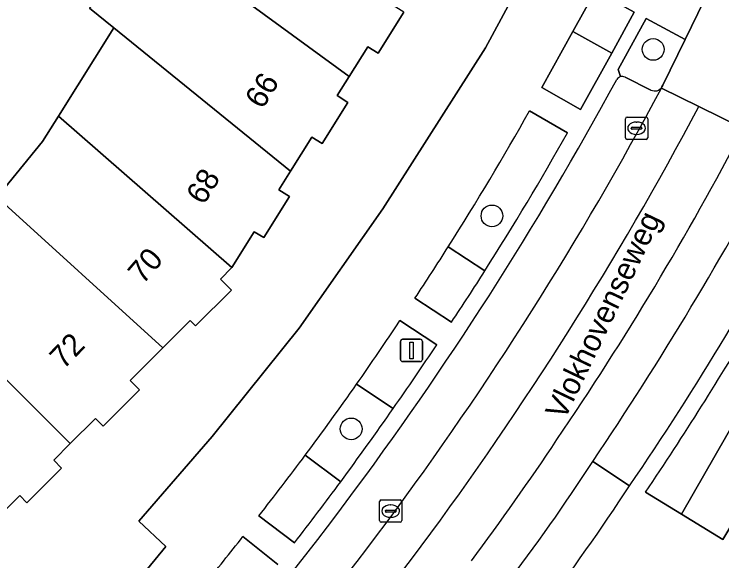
# Model space of a CAD drawing. Extents: x 161354 to 162026, y 386504 to 387460.
# Drawn here: x 161596.6 to 161628.46, y 386881.71 to 386906.3 of the extents above; entities that cross this region are included whole.
import ezdxf

# ---------------------------------------------------------------- set-up
doc = ezdxf.new("R2010")
doc.units = 0
for name, color, linetype in [('IMGEO_Boom', 7, 'Continuous'), ('IMGEO_Erf', 7, 'Continuous'), ('IMGEO_Groenvoorziening', 7, 'Continuous'), ('IMGEO_Kolk', 7, 'Continuous'), ('IMGEO_Lichtmast', 7, 'Continuous'), ('IMGEO_Openbare_ruimte_label', 7, 'Continuous'), ('IMGEO_Pand', 7, 'Continuous'), ('IMGEO_Pand_nummerreeks', 7, 'Continuous'), ('IMGEO_Parkeervlak_open', 7, 'Continuous'), ('IMGEO_Rijbaan_lokaal_gesloten', 7, 'Continuous'), ('IMGEO_Rijbaan_lokaal_open', 7, 'Continuous'), ('IMGEO_Voetpad_open', 7, 'Continuous')]:
    doc.layers.add(name, color=color, linetype=linetype)

msp = doc.modelspace()

# ---------------------------------------------------------------- linework, layer by layer
at = {"layer": 'IMGEO_Boom'}
for centre in [(161625.366, 386904.718), (161618.11, 386897.228), (161611.772, 386887.643)]:
    msp.add_circle(centre, 0.489, dxfattribs=at)
at = {"layer": 'IMGEO_Erf'}
for points in [[(161601.088, 386879.5), (161603.425, 386882.36), (161602.205, 386883.499), (161605.511, 386887.3), (161609.426, 386892.17), (161613.199, 386897.541), (161617.812, 386904.79), (161621.155, 386910.96), (161615.666, 386914.035), (161613.626, 386916.073), (161610.545, 386917.769), (161608.974, 386918.547), (161607.34, 386919.182), (161605.655, 386919.668), (161604.896, 386919.835), (161603.346, 386920.042), (161602.754, 386919.169), (161601.089, 386916.715), (161599.424, 386914.261), (161597.317, 386915.691), (161595.992, 386913.34), (161598.099, 386911.91), (161596.434, 386909.456)], [(161614.148, 386906.394), (161612.989, 386904.544), (161612.517, 386904.84), (161611.674, 386903.494), (161611.14, 386902.642), (161611.628, 386902.336), (161610.467, 386900.482), (161610.001, 386900.774), (161609.038, 386899.236), (161608.514, 386898.399), (161608.991, 386898.1), (161607.832, 386896.25), (161607.409, 386896.515), (161606.397, 386894.899), (161605.885, 386894.387), (161606.378, 386893.893), (161604.76, 386892.278), (161604.522, 386892.517), (161603.288, 386891.286), (161601.818, 386889.818), (161602.236, 386889.399), (161600.605, 386887.771), (161600.261, 386888.116), (161599.124, 386886.982), (161598.38, 386886.239), (161598.735, 386885.884), (161597.172, 386884.323), (161596.848, 386884.648), (161595.588, 386883.391)], [(161595.815, 386898.067), (161597.876, 386900.568), (161598.596, 386901.718), (161601.082, 386905.687), (161599.987, 386906.575)]]:
    msp.add_lwpolyline(points, dxfattribs=at)
at = {"layer": 'IMGEO_Groenvoorziening'}
for points in [[(161624.515, 386906.389), (161622.768, 386907.364), (161621.746, 386905.523), (161623.499, 386904.549)], [(161621.746, 386905.523), (161620.349, 386903.005), (161622.102, 386902.02), (161623.499, 386904.549)], [(161633.249, 386890.619), (161631.253, 386891.827), (161626.635, 386883.81), (161628.505, 386882.663)]]:
    msp.add_lwpolyline(points, close=True, dxfattribs=at)
for points in [[(161626.801, 386905.161), (161625.051, 386906.108), (161623.791, 386903.815), (161623.901, 386903.492)], [(161625.763, 386903.031), (161625.799, 386903.114), (161626.801, 386905.161)], [(161624.099, 386903.472), (161625.268, 386902.889)], [(161621.512, 386900.967), (161619.798, 386901.947)], [(161616.143, 386895.841), (161617.793, 386894.758)], [(161617.793, 386894.758), (161616.143, 386895.841)], [(161614.64, 386893.523), (161616.289, 386892.447)], [(161615.622, 386891.432), (161613.966, 386892.515)], [(161625.025, 386884.797), (161626.635, 386883.81), (161631.253, 386891.827)], [(161613.664, 386888.559), (161612.012, 386889.653)], [(161612.012, 386889.653), (161613.664, 386888.559)], [(161609.701, 386886.457), (161611.3, 386885.271)], [(161611.3, 386885.271), (161609.701, 386886.457)], [(161607.615, 386883.731), (161609.221, 386882.526)], [(161608.476, 386881.546), (161606.897, 386882.798)]]:
    msp.add_lwpolyline(points, dxfattribs=at)
for centre, radius, start, end in [((161623.973, 386903.219), 0.282, 63.602, 104.8622), ((161625.44, 386903.222), 0.375, 242.5924, 329.4206), ((161500.36, 386969.295), 137.118, 327.60864, 330.5826), ((161504.13, 386967.057), 134.708, 327.54032, 330.61906), ((161497.522, 386971.109), 140.486, 326.47711, 327.60384), ((161502.238, 386968.316), 136.981, 326.36724, 327.52057), ((161498.371, 386969.338), 138.795, 324.96181, 326.39241), ((161490.613, 386975.069), 161.913, 326.11426, 329.38467), ((161486.034, 386977.645), 155.646, 325.08494, 326.36482), ((161497.604, 386969.947), 139.772, 323.32124, 324.93803), ((161488.847, 386975.806), 152.287, 323.52286, 325.04652), ((161491.692, 386974.599), 147.293, 321.90829, 323.24356), ((161490.956, 386974.257), 149.67, 322.20143, 323.51966), ((161486.485, 386977.923), 153.453, 320.64443, 321.69126)]:
    msp.add_arc(centre, radius, start, end, dxfattribs=at)
at = {"layer": 'IMGEO_Kolk'}
for p, q in [((161624.119, 386900.746), (161624.119, 386901.598)), ((161624.194, 386901.672), (161625.046, 386901.672)), ((161625.12, 386901.598), (161625.12, 386900.746)), ((161624.607, 386901.452), (161624.632, 386901.452)), ((161624.378, 386901.166), (161624.378, 386901.178)), ((161624.816, 386901.129), (161624.418, 386901.129)), ((161624.421, 386901.215), (161624.819, 386901.215)), ((161624.862, 386901.178), (161624.862, 386901.166)), ((161625.046, 386900.672), (161624.194, 386900.672)), ((161624.63, 386900.892), (161624.605, 386900.892)), ((161613.05, 386883.521), (161613.05, 386884.373)), ((161613.125, 386884.447), (161613.977, 386884.447)), ((161614.051, 386884.373), (161614.051, 386883.521)), ((161613.538, 386884.227), (161613.563, 386884.227)), ((161613.309, 386883.941), (161613.309, 386883.953)), ((161613.747, 386883.904), (161613.349, 386883.904)), ((161613.352, 386883.99), (161613.75, 386883.99)), ((161613.793, 386883.953), (161613.793, 386883.941)), ((161613.977, 386883.447), (161613.125, 386883.447)), ((161613.561, 386883.667), (161613.536, 386883.667))]:
    msp.add_line(p, q, dxfattribs=at)
for points in [[(161624.119, 386900.746), (161624.119, 386901.598)], [(161624.194, 386901.672), (161625.046, 386901.672)], [(161625.12, 386901.598), (161625.12, 386900.746)], [(161625.046, 386900.672), (161624.194, 386900.672)], [(161613.05, 386883.521), (161613.05, 386884.373)], [(161613.125, 386884.447), (161613.977, 386884.447)], [(161614.051, 386884.373), (161614.051, 386883.521)], [(161613.977, 386883.447), (161613.125, 386883.447)]]:
    msp.add_lwpolyline(points, dxfattribs=at)
for centre, radius, start, end in [((161624.196, 386901.596), 0.0765, 91.552, 178.448), ((161624.196, 386901.596), 0.0765, 91.552, 178.448), ((161625.044, 386901.596), 0.0765, 1.552, 88.448), ((161625.044, 386901.596), 0.0765, 1.552, 88.448), ((161624.418, 386901.175), 0.0403, 85.8775, 175.7526), ((161624.415, 386901.165), 0.0366, 178.938, 274.7102), ((161624.819, 386901.172), 0.043, 264.8664, 352.4533), ((161624.823, 386901.177), 0.0386, 1.7309, 96.639), ((161624.196, 386900.748), 0.0765, 181.552, 268.448), ((161624.196, 386900.748), 0.0765, 181.552, 268.448), ((161625.044, 386900.748), 0.0765, 271.552, 358.448), ((161625.044, 386900.748), 0.0765, 271.552, 358.448), ((161613.127, 386884.371), 0.0765, 91.552, 178.448), ((161613.127, 386884.371), 0.0765, 91.552, 178.448), ((161613.975, 386884.371), 0.0765, 1.552, 88.448), ((161613.975, 386884.371), 0.0765, 1.552, 88.448), ((161613.349, 386883.95), 0.0403, 85.8775, 175.7526), ((161613.346, 386883.94), 0.0366, 178.938, 274.7102), ((161613.75, 386883.947), 0.043, 264.8664, 352.4533), ((161613.754, 386883.952), 0.0386, 1.7309, 96.639), ((161613.127, 386883.523), 0.0765, 181.552, 268.448), ((161613.127, 386883.523), 0.0765, 181.552, 268.448), ((161613.975, 386883.523), 0.0765, 271.552, 358.448), ((161613.975, 386883.523), 0.0765, 271.552, 358.448)]:
    msp.add_arc(centre, radius, start, end, dxfattribs=at)
for centre, major_axis, ratio, start_param, end_param in [((161624.606, 386901.172), (-0.387, 0.002), 0.722429, 4.712389, 7.853982), ((161624.631, 386901.172), (-0.39, 0.002), 0.717154, 1.570796, 4.712389), ((161613.537, 386883.947), (-0.387, 0.002), 0.722429, 4.712389, 7.853982), ((161613.562, 386883.947), (-0.39, 0.002), 0.717154, 1.570796, 4.712389)]:
    msp.add_ellipse(centre, major_axis=major_axis, ratio=ratio, start_param=start_param, end_param=end_param, dxfattribs=at)
at = {"layer": 'IMGEO_Lichtmast'}
for p, q in [((161613.989, 386890.775), (161613.989, 386891.575)), ((161613.989, 386891.575), (161613.989, 386890.775)), ((161614.089, 386891.675), (161614.879, 386891.675)), ((161614.879, 386891.675), (161614.089, 386891.675)), ((161614.979, 386891.575), (161614.979, 386890.775)), ((161614.979, 386890.775), (161614.979, 386891.575)), ((161614.879, 386890.675), (161614.089, 386890.675)), ((161614.089, 386890.675), (161614.879, 386890.675))]:
    msp.add_line(p, q, dxfattribs=at)
msp.add_lwpolyline([(161614.409, 386891.55), (161614.559, 386891.55), (161614.559, 386890.8), (161614.409, 386890.8), (161614.409, 386891.55)], dxfattribs=at)
for centre, start, end in [((161614.089, 386891.575), 90, 180), ((161614.089, 386891.575), 90, 180), ((161614.879, 386891.575), 0, 90), ((161614.879, 386891.575), 360, 90), ((161614.089, 386890.775), 180, 270), ((161614.089, 386890.775), 180, 270), ((161614.879, 386890.775), 270, 0), ((161614.879, 386890.775), 270, 0)]:
    msp.add_arc(centre, 0.1, start, end, dxfattribs=at)
at = {"layer": 'IMGEO_Pand'}
for points in [[(161605.816, 386913.247), (161605.633, 386912.954), (161603.469, 386909.498), (161611.674, 386903.494), (161612.517, 386904.84), (161612.989, 386904.544), (161614.148, 386906.394), (161613.665, 386906.697), (161614.403, 386907.875)], [(161603.469, 386909.498), (161602.337, 386910.326), (161599.987, 386906.575), (161601.082, 386905.687), (161609.038, 386899.236), (161610.001, 386900.774), (161610.467, 386900.482), (161611.628, 386902.336), (161611.14, 386902.642), (161611.674, 386903.494)], [(161601.082, 386905.687), (161598.596, 386901.718), (161606.397, 386894.899), (161607.409, 386896.515), (161607.832, 386896.25), (161608.991, 386898.1), (161608.514, 386898.399), (161609.038, 386899.236)], [(161603.288, 386891.286), (161604.522, 386892.517), (161604.76, 386892.278), (161606.378, 386893.893), (161605.885, 386894.387), (161606.397, 386894.899), (161598.596, 386901.718), (161597.876, 386900.568), (161595.815, 386898.067)], [(161595.815, 386898.067), (161595.252, 386897.383), (161591.968, 386894.106), (161599.124, 386886.982), (161600.261, 386888.116), (161600.605, 386887.771), (161602.236, 386889.399), (161601.818, 386889.818), (161603.288, 386891.286)], [(161591.968, 386894.106), (161591.789, 386893.897), (161591.171, 386894.516), (161591.142, 386894.488), (161587.794, 386891.147), (161588.4, 386890.544), (161595.588, 386883.391), (161596.848, 386884.648), (161597.172, 386884.323), (161598.735, 386885.884), (161598.38, 386886.239), (161599.124, 386886.982)]]:
    msp.add_lwpolyline(points, close=True, dxfattribs=at)
at = {"layer": 'IMGEO_Parkeervlak_open'}
for points in [[(161625.268, 386902.889), (161624.099, 386903.472)], [(161625.741, 386902.981), (161625.763, 386903.031)], [(161622.644, 386886.181), (161624.304, 386885.086)]]:
    msp.add_lwpolyline(points, dxfattribs=at)
for centre, radius, start, end in [((161623.973, 386903.215), 0.286, 104.4697, 149.059), ((161623.973, 386903.219), 0.282, 63.602, 104.8622), ((161486.104, 386978.178), 156.645, 314.94665, 331.47035), ((161488.936, 386975.928), 155.038, 314.79473, 331.93275), ((161625.44, 386903.222), 0.375, 242.5924, 329.4206), ((161494.394, 386972.85), 154.789, 325.94983, 332.04142), ((161506.276, 386965.708), 142.935, 325.66388, 332.09614)]:
    msp.add_arc(centre, radius, start, end, dxfattribs=at)
at = {"layer": 'IMGEO_Rijbaan_lokaal_gesloten'}
msp.add_lwpolyline([(161627.425, 386902.148), (161625.741, 386902.981)], dxfattribs=at)
for centre, radius, start, end in [((161488.936, 386975.928), 155.038, 314.79473, 331.93275), ((161489.991, 386975.192), 155.639, 314.76332, 332.01003), ((161502.557, 386967.817), 143.323, 325.75385, 332.28494), ((161494.394, 386972.85), 154.789, 325.94983, 332.04142), ((161518.961, 386955.119), 122.624, 323.2265, 326.34491), ((161545.338, 386936.322), 92.143, 322.75185, 327.03221)]:
    msp.add_arc(centre, radius, start, end, dxfattribs=at)
at = {"layer": 'IMGEO_Rijbaan_lokaal_open'}
for points in [[(161628.236, 386908.1), (161626.801, 386905.161), (161625.799, 386903.114), (161625.763, 386903.031), (161625.741, 386902.981), (161627.425, 386902.148), (161629.437, 386901.161), (161631.15, 386900.341), (161632.194, 386902.501), (161630.512, 386903.319), (161638.615, 386919.995), (161640.317, 386919.149)], [(161629.437, 386901.161), (161627.425, 386902.148)], [(161624.304, 386885.086), (161622.644, 386886.181)]]:
    msp.add_lwpolyline(points, dxfattribs=at)
for centre, radius, start, end in [((161489.991, 386975.192), 155.639, 314.76332, 332.01003), ((161502.557, 386967.817), 143.323, 325.75385, 332.28494), ((161518.961, 386955.119), 122.624, 323.2265, 326.34491), ((161545.338, 386936.322), 92.143, 322.75185, 327.03221), ((161530.465, 386946.83), 112.33, 323.09255, 326.65596)]:
    msp.add_arc(centre, radius, start, end, dxfattribs=at)
at = {"layer": 'IMGEO_Voetpad_open'}
for points in [[(161626.684, 386914.559), (161624.541, 386915.869), (161621.155, 386910.96), (161617.812, 386904.79), (161613.199, 386897.541), (161609.426, 386892.17), (161605.511, 386887.3), (161602.205, 386883.499), (161603.425, 386882.36), (161601.088, 386879.5), (161596.783, 386874.819), (161589.161, 386867.257), (161578.702, 386858.612), (161569.609, 386852.318), (161562.581, 386848.097), (161561.221, 386847.589), (161545.191, 386839.884), (161543.789, 386836.438), (161541.337, 386835.451), (161537.295, 386833.825), (161536.546, 386833.523), (161529.161, 386831.19), (161515.819, 386828.343), (161514.452, 386828.372)], [(161623.901, 386903.492), (161623.791, 386903.815), (161625.051, 386906.108), (161626.801, 386905.161), (161628.236, 386908.1)], [(161619.798, 386901.947), (161621.512, 386900.967)], [(161616.289, 386892.447), (161614.64, 386893.523)], [(161613.966, 386892.515), (161615.622, 386891.432)], [(161629.956, 386892.612), (161631.253, 386891.827), (161633.249, 386890.619), (161628.505, 386882.663), (161626.635, 386883.81), (161625.025, 386884.797)], [(161609.221, 386882.526), (161607.615, 386883.731)], [(161606.897, 386882.798), (161608.476, 386881.546)]]:
    msp.add_lwpolyline(points, dxfattribs=at)
msp.add_lwpolyline([(161620.349, 386903.005), (161621.746, 386905.523), (161622.768, 386907.364), (161624.515, 386906.389), (161623.499, 386904.549), (161622.102, 386902.02)], close=True, dxfattribs=at)
for centre, radius, start, end in [((161623.973, 386903.215), 0.286, 104.4697, 149.059), ((161486.104, 386978.178), 156.645, 314.94665, 331.47035), ((161500.36, 386969.295), 137.118, 327.60864, 330.5826), ((161504.13, 386967.057), 134.708, 327.54032, 330.61906), ((161506.276, 386965.708), 142.935, 325.66388, 332.09614), ((161497.522, 386971.109), 140.486, 326.47711, 327.60384), ((161502.238, 386968.316), 136.981, 326.36724, 327.52057), ((161498.371, 386969.338), 138.795, 324.96181, 326.39241), ((161490.613, 386975.069), 161.913, 326.11426, 329.38467), ((161486.034, 386977.645), 155.646, 325.08494, 326.36482), ((161497.604, 386969.947), 139.772, 323.32124, 324.93803), ((161488.847, 386975.806), 152.287, 323.52286, 325.04652), ((161491.692, 386974.599), 147.293, 321.90829, 323.24356), ((161490.956, 386974.257), 149.67, 322.20143, 323.51966), ((161530.465, 386946.83), 112.33, 323.09255, 326.65596), ((161486.485, 386977.923), 153.453, 320.64443, 321.69126)]:
    msp.add_arc(centre, radius, start, end, dxfattribs=at)

# ---------------------------------------------------------------- texts
at = {"layer": 'IMGEO_Openbare_ruimte_label'}
msp.add_text('Vlokhovenseweg', height=1, rotation=64.4086, dxfattribs=at).set_placement((161621.373, 386887.999))
at = {"layer": 'IMGEO_Pand_nummerreeks'}
for s, rotation, p in [('66', 58.2412, (161607.779, 386901.988)), ('68', 58.6588, (161605.136, 386897.675)), ('70', 49.2945, (161602.395, 386894.112)), ('72', 45.9463, (161598.819, 386890.29))]:
    msp.add_text(s, height=1, rotation=rotation, dxfattribs=at).set_placement(p)

doc.saveas('drawing.dxf')
